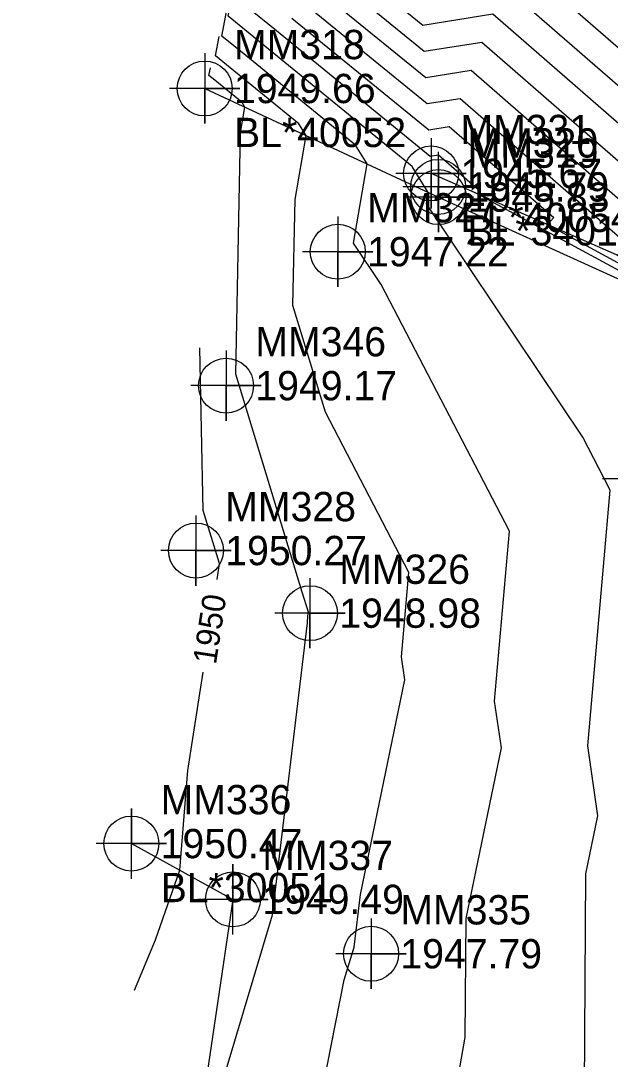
# Model space of a CAD drawing. Extents: x 1004378 to 1005103, y 553854 to 554288.
# Drawn here: x 1004892.9 to 1004943.2, y 554030.8 to 554119.4 of the extents above; entities that cross this region are included whole.
import ezdxf

# ---------------------------------------------------------------- set-up
doc = ezdxf.new("R2010")
doc.units = 0
for name, color, linetype in [('DTM Contours Major', 7, 'Continuous'), ('DTM Contours Major Text', 7, 'Continuous'), ('DTM Contours Minor', 7, 'Continuous'), ('Exist Building Cogo Elevation', 7, 'Continuous'), ('Exist Building Cogo Number', 7, 'Continuous'), ('Exist Building Cogo Point CELL', 7, 'Continuous'), ('Exist DTM Breakline', 7, 'Continuous'), ('Exist DTM Breakline Cogo Comment', 7, 'Continuous'), ('Exist DTM Breakline Cogo Elevation', 7, 'Continuous'), ('Exist DTM Breakline Cogo Number', 7, 'Continuous'), ('Exist DTM Breakline Cogo Point CELL', 7, 'Continuous'), ('Exist DTM Regular Point CELL', 7, 'Continuous'), ('Exist DTM Regular Point Cogo Elevation', 7, 'Continuous'), ('Exist DTM Regular Point Cogo Number', 7, 'Continuous'), ('Exist Roads Soil', 7, 'Continuous'), ('Exist Roads Soil Cogo Comment', 7, 'Continuous'), ('Exist Roads Soil Cogo Elevation', 7, 'Continuous'), ('Exist Roads Soil Cogo Number', 7, 'Continuous'), ('Exist Roads Soil Cogo Point CELL', 7, 'Continuous')]:
    doc.layers.add(name, color=color, linetype=linetype)

msp = doc.modelspace()

# ---------------------------------------------------------------- linework, layer by layer
at = {"layer": 'DTM Contours Major'}
for points in [[(1004915.782, 554139.515), (1004913.904, 554129.888), (1004921.295, 554123.861), (1004927.208, 554119.035), (1004933.185, 554119.992), (1004950.058, 554105.284), (1004959.128, 554107.116), (1004955.463, 554097.569), (1004955.218, 554096.276), (1004954.505, 554094.696), (1004954.285, 554093.293), (1004951.079, 554078.342), (1004951.712, 554073.035)], [(1004912.064, 554126.115), (1004911.158, 554121.47), (1004914.724, 554118.563), (1004927.833, 554107.862), (1004928.535, 554107.974), (1004932.097, 554104.869), (1004931.879, 554104.636), (1004950.839, 554094.361), (1004950.581, 554093.249), (1004946.204, 554080.072), (1004948.75, 554054.444), (1004948.799, 554054.036), (1004948.807, 554053.997), (1004948.82, 554053.955), (1004947.217, 554049.061)], [(1004909.665, 554071.743), (1004909.872, 554073.096), (1004908.478, 554077.615), (1004908.182, 554091.498)], [(1004902.606, 554036.691), (1004904.394, 554040.979), (1004906.491, 554046.924), (1004907.174, 554055.43), (1004908.457, 554063.834)]]:
    msp.add_lwpolyline(points, dxfattribs=at)
at = {"layer": 'DTM Contours Minor'}
for points in [[(1004935.046, 554124.799), (1004945.367, 554115.802), (1004966.063, 554119.983), (1004957.7, 554098.197), (1004957.141, 554095.246), (1004956.493, 554093.81), (1004955.969, 554090.464), (1004953.229, 554077.683), (1004955.169, 554061.406), (1004956.161, 554056.646), (1004957.691, 554051.606), (1004956.558, 554048.146), (1004956.724, 554029.339)], [(1004892.909, 553980.228), (1004909.736, 553977.519), (1004919.988, 553982.517), (1004925.173, 553984.426), (1004936.898, 553999.835), (1004937.254, 554000.219), (1004937.418, 554000.896), (1004939.715, 554013.407), (1004939.746, 554016.607), (1004940.982, 554023.681), (1004941.12, 554046.622), (1004942.146, 554051.575), (1004941.271, 554057.545), (1004943.194, 554079.367), (1004940.844, 554083.886), (1004927.509, 554103.798), (1004927.675, 554104.761), (1004926.297, 554106.983), (1004913.409, 554117.504), (1004910.609, 554119.787), (1004911.321, 554123.435)], [(1004919.981, 554122.802), (1004927.333, 554116.8), (1004932.255, 554117.588), (1004952.404, 554100.025), (1004955.66, 554100.683), (1004954.344, 554097.255), (1004954.256, 554096.791), (1004953.511, 554095.139), (1004953.443, 554094.708), (1004950.005, 554078.671), (1004952.439, 554058.248), (1004953.009, 554055.511), (1004953.889, 554052.612), (1004952.484, 554048.322), (1004952.69, 554025)], [(1004934.115, 554122.395), (1004947.713, 554110.543), (1004962.595, 554113.55), (1004956.581, 554097.883), (1004956.179, 554095.761), (1004955.499, 554094.253), (1004955.127, 554091.879), (1004952.154, 554078.013), (1004954.259, 554060.353), (1004955.111, 554056.268), (1004956.424, 554051.941), (1004955.2, 554048.205), (1004955.379, 554027.893)], [(1004918.667, 554121.742), (1004927.458, 554114.566), (1004931.325, 554115.185), (1004950.953, 554098.075), (1004949.754, 554096.79), (1004952.721, 554095.183), (1004949.04, 554079.301), (1004948.941, 554079.002), (1004948.999, 554078.42), (1004951.529, 554057.195), (1004951.959, 554055.132), (1004952.622, 554052.948), (1004951.126, 554048.381), (1004951.345, 554023.554)], [(1004896.871, 553987.94), (1004907.319, 553986.258), (1004918.577, 553991.746), (1004920.602, 553996.072), (1004926.171, 554004.786), (1004927.401, 554011.483), (1004927.417, 554013.109), (1004930.834, 554032.674), (1004930.895, 554042.816), (1004933.912, 554057.37), (1004933.33, 554061.338), (1004934.608, 554075.845), (1004923.665, 554096.889), (1004921.296, 554100.426), (1004922.463, 554107.183), (1004921.461, 554108.798), (1004912.095, 554116.444), (1004910.06, 554118.103), (1004910.577, 554120.754)], [(1004917.352, 554120.683), (1004927.583, 554112.331), (1004930.395, 554112.781), (1004944.668, 554100.34), (1004943.796, 554099.406), (1004952.093, 554094.909), (1004949.554, 554083.951), (1004948.029, 554079.359), (1004948.916, 554070.428), (1004950.619, 554056.142), (1004950.908, 554054.754), (1004951.354, 554053.283), (1004949.768, 554048.44), (1004950.001, 554022.107)], [(1004916.038, 554119.623), (1004927.708, 554110.097), (1004929.465, 554110.378), (1004938.382, 554102.604), (1004937.837, 554102.021), (1004951.466, 554094.635), (1004950.068, 554088.6), (1004947.116, 554079.715), (1004948.833, 554062.436), (1004949.709, 554055.089), (1004949.858, 554054.375), (1004950.087, 554053.619), (1004948.41, 554048.498), (1004948.656, 554020.661)], [(1004900.833, 553995.652), (1004904.901, 553994.997), (1004909.285, 553997.134), (1004914.864, 554009.051), (1004915.047, 554009.338), (1004915.087, 554009.558), (1004915.088, 554009.611), (1004915.812, 554013.756), (1004920.511, 554037.575), (1004921.349, 554040.369), (1004921.885, 554044.869), (1004925.677, 554063.164), (1004925.388, 554065.131), (1004926.022, 554072.322), (1004918.902, 554086.015), (1004916.128, 554095.112), (1004916.311, 554104.166), (1004917.251, 554109.606), (1004916.626, 554110.613), (1004910.781, 554115.385), (1004909.511, 554116.42), (1004909.834, 554118.074)], [(1004903.159, 554010.176), (1004907.034, 554019.468), (1004908.926, 554023.854), (1004909.52, 554026.862), (1004914.391, 554043.11), (1004917.359, 554068.029), (1004917.408, 554068.634), (1004917.453, 554068.931), (1004916.926, 554070.64), (1004911.247, 554089.262), (1004911.665, 554109.865), (1004912.038, 554112.028), (1004911.79, 554112.428), (1004909.467, 554114.325), (1004908.962, 554114.737), (1004909.09, 554115.394)]]:
    msp.add_lwpolyline(points, dxfattribs=at)
at = {"layer": 'Exist Building Cogo Point CELL'}
msp.add_lwpolyline([(1004928.515, 554108.229), (1004928.515, 554102.229), (1004928.515, 554105.229), (1004931.515, 554105.229), (1004925.515, 554105.229)], dxfattribs=at)
msp.add_circle((1004928.515, 554105.229), 2.344, dxfattribs=at)
at = {"layer": 'Exist DTM Breakline'}
for points in [[(1004908.599, 554113.626), (1004928.542, 554104.358), (1004950.697, 554094.299), (1004945.541, 554080.331), (1004948.745, 554053.974), (1004946.395, 554048.586), (1004946.774, 554014.511), (1004946.946, 553994.845), (1004942.426, 553964.624), (1004933.56, 553959.38), (1004919.92, 553960.138), (1004910.869, 553961.543), (1004894.885, 553951.978), (1004894.101, 553924.52), (1004896.848, 553886.739), (1004896.026, 553883.694)], [(1004949.005, 554078.977), (1004953.07, 554095.335), (1004927.916, 554106.376)]]:
    msp.add_lwpolyline(points, dxfattribs=at)
at = {"layer": 'Exist DTM Breakline Cogo Point CELL'}
for points in [[(1004908.599, 554116.626), (1004908.599, 554110.626), (1004908.599, 554113.626), (1004911.599, 554113.626), (1004905.599, 554113.626)], [(1004927.916, 554109.376), (1004927.916, 554103.376), (1004927.916, 554106.376), (1004930.916, 554106.376), (1004924.916, 554106.376)], [(1004928.542, 554107.358), (1004928.542, 554101.358), (1004928.542, 554104.358), (1004931.542, 554104.358), (1004925.542, 554104.358)], [(1004945.541, 554083.331), (1004945.541, 554077.331), (1004945.541, 554080.331), (1004948.541, 554080.331), (1004942.541, 554080.331)]]:
    msp.add_lwpolyline(points, dxfattribs=at)
for centre in [(1004908.599, 554113.626), (1004927.916, 554106.376), (1004928.542, 554104.358)]:
    msp.add_circle(centre, 2.344, dxfattribs=at)
at = {"layer": 'Exist DTM Regular Point CELL'}
for points in [[(1004919.954, 554102.698), (1004919.954, 554096.698), (1004919.954, 554099.698), (1004922.954, 554099.698), (1004916.954, 554099.698)], [(1004910.421, 554091.271), (1004910.421, 554085.271), (1004910.421, 554088.271), (1004913.421, 554088.271), (1004907.421, 554088.271)], [(1004907.856, 554077.204), (1004907.856, 554071.204), (1004907.856, 554074.204), (1004910.856, 554074.204), (1004904.856, 554074.204)], [(1004917.583, 554071.86), (1004917.583, 554065.86), (1004917.583, 554068.86), (1004920.583, 554068.86), (1004914.583, 554068.86)], [(1004922.794, 554042.8), (1004922.794, 554036.8), (1004922.794, 554039.8), (1004925.794, 554039.8), (1004919.794, 554039.8)]]:
    msp.add_lwpolyline(points, dxfattribs=at)
for centre in [(1004919.954, 554099.698), (1004910.421, 554088.271), (1004907.856, 554074.204), (1004917.583, 554068.86), (1004922.794, 554039.8)]:
    msp.add_circle(centre, 2.344, dxfattribs=at)
at = {"layer": 'Exist Roads Soil'}
msp.add_lwpolyline([(1004902.345, 554049.201), (1004911.013, 554044.44), (1004908.227, 554025.602), (1004914.669, 554009.493), (1004937.036, 554000.34), (1004928.257, 553968.154), (1004911.901, 553969.693), (1004894.395, 553961.828)], dxfattribs=at)
at = {"layer": 'Exist Roads Soil Cogo Point CELL'}
for points in [[(1004902.345, 554046.201), (1004902.345, 554052.201), (1004902.345, 554049.201), (1004905.345, 554049.201), (1004899.345, 554049.201)], [(1004911.013, 554041.44), (1004911.013, 554047.44), (1004911.013, 554044.44), (1004914.013, 554044.44), (1004908.013, 554044.44)]]:
    msp.add_lwpolyline(points, dxfattribs=at)
for centre in [(1004902.345, 554049.201), (1004911.013, 554044.44)]:
    msp.add_circle(centre, 2.344, dxfattribs=at)

# ---------------------------------------------------------------- texts
at = {"layer": 'DTM Contours Major Text'}
msp.add_text('1950', height=2, rotation=81.31604, dxfattribs=at).set_placement((1004909.559, 554064.423))
at = {"layer": 'Exist Building Cogo Elevation'}
for s, p in [('1945.79', (1004931.015, 554103.979)), ('BL*34013', (1004931.015, 554100.229))]:
    msp.add_text(s, height=2.5, dxfattribs=at).set_placement(p)
at = {"layer": 'Exist Building Cogo Number'}
msp.add_text('MM320', height=2.5, dxfattribs=at).set_placement((1004931.015, 554107.729))
at = {"layer": 'Exist DTM Breakline Cogo Comment'}
for s, p in [('BL*40052', (1004911.099, 554108.626)), ('EL*40054', (1004930.416, 554101.376))]:
    msp.add_text(s, height=2.5, dxfattribs=at).set_placement(p)
at = {"layer": 'Exist DTM Breakline Cogo Elevation'}
for s, p in [('1949.66', (1004911.099, 554112.376)), ('1945.67', (1004930.416, 554105.126)), ('1945.83', (1004931.042, 554103.108))]:
    msp.add_text(s, height=2.5, dxfattribs=at).set_placement(p)
at = {"layer": 'Exist DTM Breakline Cogo Number'}
for s, p in [('MM318', (1004911.099, 554116.126)), ('MM331', (1004930.416, 554108.876)), ('MM319', (1004931.042, 554106.858))]:
    msp.add_text(s, height=2.5, dxfattribs=at).set_placement(p)
at = {"layer": 'Exist DTM Regular Point Cogo Elevation'}
for s, p in [('1947.22', (1004922.454, 554098.448)), ('1949.17', (1004912.921, 554087.021)), ('1950.27', (1004910.356, 554072.954)), ('1948.98', (1004920.083, 554067.61)), ('1947.79', (1004925.294, 554038.55))]:
    msp.add_text(s, height=2.5, dxfattribs=at).set_placement(p)
at = {"layer": 'Exist DTM Regular Point Cogo Number'}
for s, p in [('MM327', (1004922.454, 554102.198)), ('MM346', (1004912.921, 554090.771)), ('MM328', (1004910.356, 554076.704)), ('MM326', (1004920.083, 554071.36)), ('MM335', (1004925.294, 554042.3))]:
    msp.add_text(s, height=2.5, dxfattribs=at).set_placement(p)
at = {"layer": 'Exist Roads Soil Cogo Comment'}
msp.add_text('BL*30051', height=2.5, dxfattribs=at).set_placement((1004904.845, 554044.201))
at = {"layer": 'Exist Roads Soil Cogo Elevation'}
for s, p in [('1950.47', (1004904.845, 554047.951)), ('1949.49', (1004913.513, 554043.19))]:
    msp.add_text(s, height=2.5, dxfattribs=at).set_placement(p)
at = {"layer": 'Exist Roads Soil Cogo Number'}
for s, p in [('MM336', (1004904.845, 554051.701)), ('MM337', (1004913.513, 554046.94))]:
    msp.add_text(s, height=2.5, dxfattribs=at).set_placement(p)

doc.saveas('drawing.dxf')
